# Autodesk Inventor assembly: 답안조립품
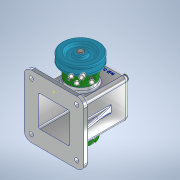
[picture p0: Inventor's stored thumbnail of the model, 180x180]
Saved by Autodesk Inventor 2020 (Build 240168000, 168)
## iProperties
Created: 2022-11
Part Number: 답안조립품
Document SubType Name: Assembly
Designer: USER
Author: USER
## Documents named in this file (17)
- C:\Users\USER\Desktop\721106V1018\답안조립품.iam
- C:\Users\USER\Desktop\721106V1018\본체.ipt.ipt
- C:\Users\USER\Desktop\721106V1018\부시.ipt
- C:\Users\USER\Desktop\721106V1018\편심축.ipt
- C:\Users\USER\Desktop\721106V1018\베어링 6201.ipt
- C:\Users\USER\Desktop\721106V1018\뒤커버.ipt
- C:\Users\USER\Desktop\721106V1018\앞커버.ipt
- C:\Users\USER\Desktop\721106V1018\볼트 M4 x 12.ipt
- C:\Users\USER\Desktop\721106V1018\링크.ipt
- C:\Users\USER\Desktop\721106V1018\슬라이드.ipt
- C:\Users\USER\Desktop\721106V1018\핀 5 x 18.ipt
- C:\Users\USER\Desktop\721106V1018\고정핀 1.2 x 10.ipt
- C:\Users\USER\Desktop\721106V1018\오일실 12 25 7.ipt
- C:\Users\USER\Desktop\721106V1018\키 4 x 4 x 15.ipt
- C:\Users\USER\Desktop\721106V1018\V벨트풀리.ipt
- C:\Users\USER\Desktop\721106V1018\멈춤나사 M3 x 8.ipt
- 본체.ipt
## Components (11 placed, 4 different names)
1. ISO 4762 M4 x 12:1
2. ISO 4762 M4 x 12:2
3. ISO 4762 M4 x 12:3
4. ISO 4762 M4 x 12:4
5. ISO 4762 M4 x 12:5
6. ISO 4762 M4 x 12:6
7. ISO 4762 M4 x 12:7
8. ISO 4762 M4 x 12:8
9. 핀 5 x 18:1
10. 고정핀 1.2 x 10:1
11. V벨트풀리:1
